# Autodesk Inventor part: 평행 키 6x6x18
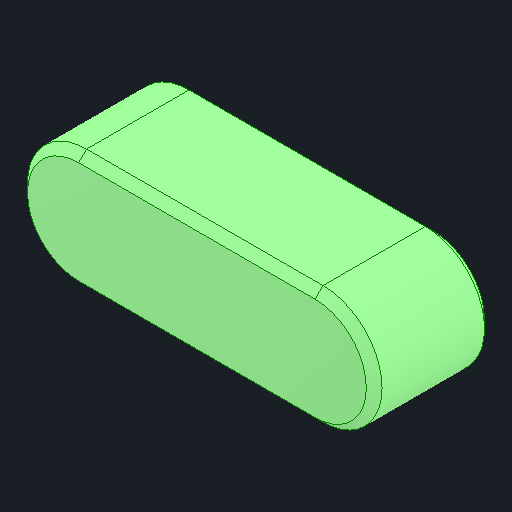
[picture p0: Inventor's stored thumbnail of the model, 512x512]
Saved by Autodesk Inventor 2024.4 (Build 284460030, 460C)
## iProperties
Created: 2026-09
Part Number: 평행 키 6x6x18
Material: 강철, 연강
Description: 키 및 해당 키홈
Document SubType Name: Modeling
Designer: user
Density: 7.85 g/cm^3
Appearance: 기본값
Author: jhkim
Sending System: Autodesk Inventor 2027
Preprocessor: ST-DEVELOPER v20.1
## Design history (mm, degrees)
feature "Solid1"
node "솔리드1"
